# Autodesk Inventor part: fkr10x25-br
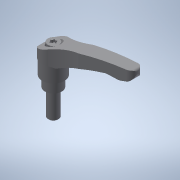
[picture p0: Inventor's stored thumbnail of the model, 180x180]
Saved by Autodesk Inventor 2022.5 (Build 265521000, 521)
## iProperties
Created: 2017-09
Part Number: fkr10x25-br
Material: 一般
Document SubType Name: Modeling
Designer: imaocorp
Density: 1 g/cm^3
Appearance: 既定
Author: imaocorp
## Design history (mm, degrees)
node "fkr10x25-br.x_t1"
node "fkr10x25-br"
node "Base1"
